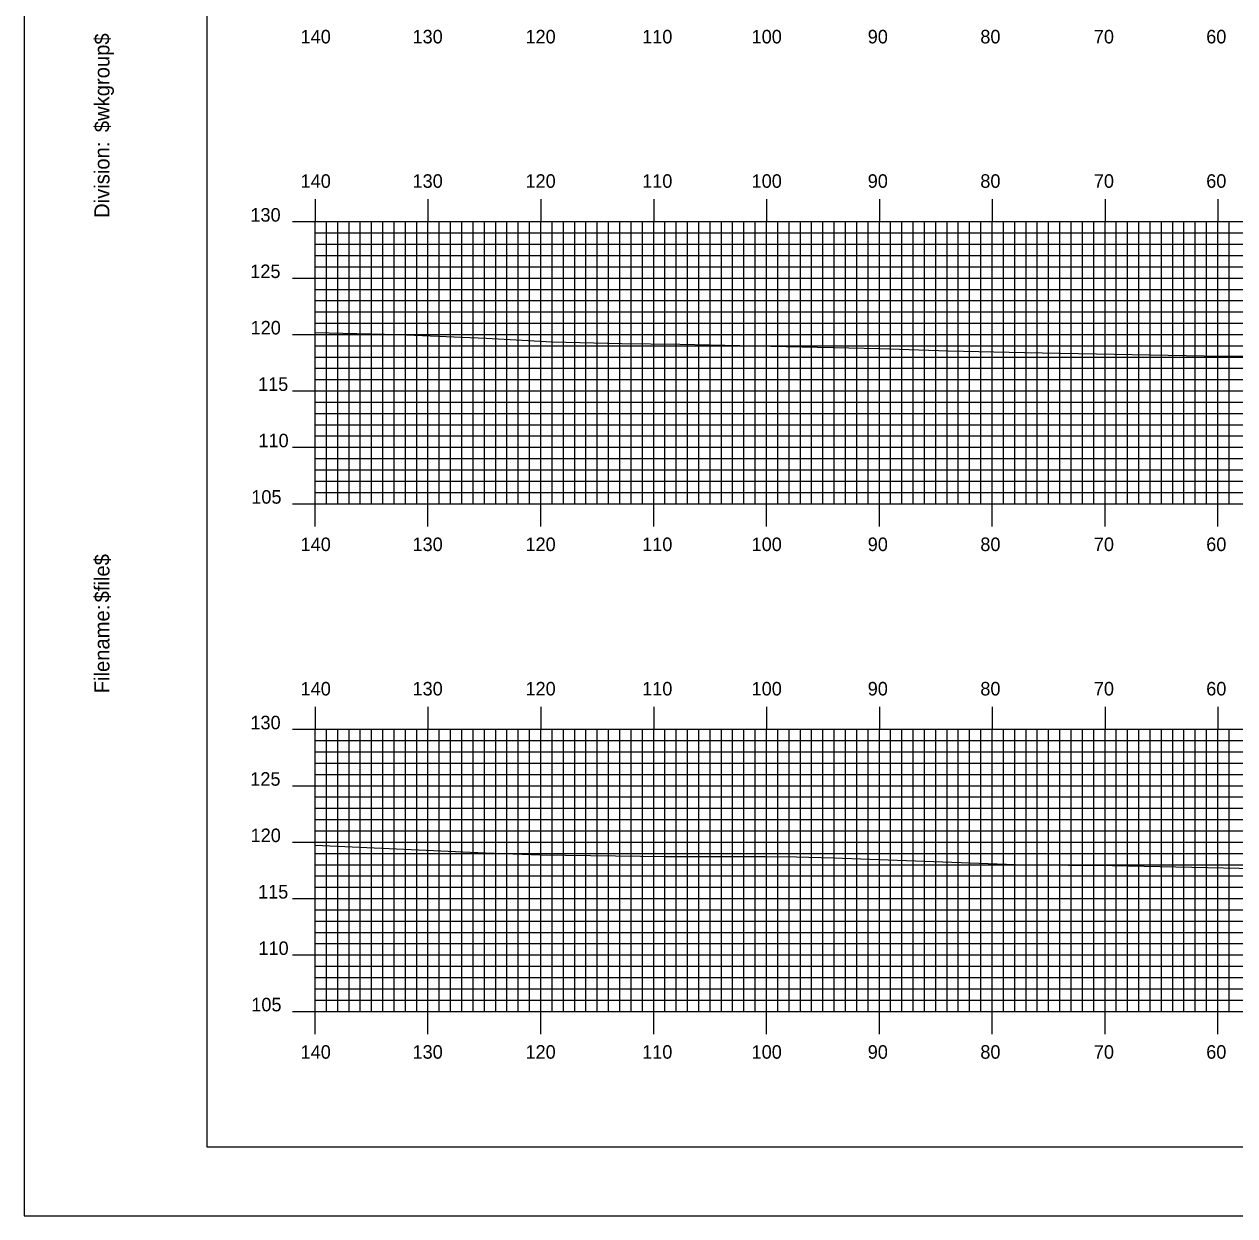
# Model space of a CAD drawing. Extents: x 1780680 to 1781023, y 442591 to 442811.
# Drawn here: x 1780679.6 to 1780786.9, y 442590.5 to 442696.2 of the extents above; entities that cross this region are included whole.
import ezdxf

# ---------------------------------------------------------------- set-up
doc = ezdxf.new("R2010")
doc.units = 0
for name, color, linetype in [('BORDER', 7, 'Continuous'), ('H_V ANNOTATION', 7, 'Continuous'), ('MAJOR', 7, 'Continuous'), ('MINOR', 7, 'Continuous'), ('PLOT BOUNDARY', 7, 'Continuous'), ('S_Roadway_Centerline', 7, 'Continuous')]:
    doc.layers.add(name, color=color, linetype=linetype)

msp = doc.modelspace()

# ---------------------------------------------------------------- linework, layer by layer
at = {"layer": 'BORDER'}
msp.add_lwpolyline([(1780695.78, 442596.67), (1781015.78, 442596.67), (1781015.78, 442806.67), (1780695.78, 442806.67)], close=True, dxfattribs=at)
at = {"layer": 'MAJOR'}
for p, q in [((1780705.38, 442680.67), (1780705.38, 442678.67)), ((1780715.38, 442680.67), (1780715.38, 442678.67)), ((1780725.38, 442680.67), (1780725.38, 442678.67)), ((1780735.38, 442680.67), (1780735.38, 442678.67)), ((1780745.38, 442680.67), (1780745.38, 442678.67)), ((1780755.38, 442680.67), (1780755.38, 442678.67)), ((1780765.38, 442680.67), (1780765.38, 442678.67)), ((1780775.38, 442680.67), (1780775.38, 442678.67)), ((1780785.38, 442680.67), (1780785.38, 442678.67)), ((1780703.38, 442678.67), (1780705.38, 442678.67)), ((1780705.38, 442678.67), (1780985.38, 442678.67)), ((1780705.38, 442653.67), (1780705.38, 442678.67)), ((1780705.38, 442653.67), (1780705.38, 442678.67)), ((1780705.38, 442678.67), (1780985.38, 442678.67)), ((1780715.38, 442653.67), (1780715.38, 442678.67)), ((1780725.38, 442653.67), (1780725.38, 442678.67)), ((1780735.38, 442653.67), (1780735.38, 442678.67)), ((1780745.38, 442653.67), (1780745.38, 442678.67)), ((1780755.38, 442653.67), (1780755.38, 442678.67)), ((1780765.38, 442653.67), (1780765.38, 442678.67)), ((1780775.38, 442653.67), (1780775.38, 442678.67)), ((1780785.38, 442653.67), (1780785.38, 442678.67)), ((1780703.38, 442673.67), (1780705.38, 442673.67)), ((1780705.38, 442673.67), (1780985.38, 442673.67)), ((1780703.38, 442668.67), (1780705.38, 442668.67)), ((1780705.38, 442668.67), (1780985.38, 442668.67)), ((1780703.38, 442663.67), (1780705.38, 442663.67)), ((1780705.38, 442663.67), (1780985.38, 442663.67)), ((1780703.38, 442658.67), (1780705.38, 442658.67)), ((1780705.38, 442658.67), (1780985.38, 442658.67)), ((1780703.38, 442653.67), (1780705.38, 442653.67)), ((1780705.38, 442653.67), (1780985.38, 442653.67)), ((1780705.38, 442653.67), (1780985.38, 442653.67)), ((1780705.38, 442651.66), (1780705.38, 442653.67)), ((1780715.38, 442651.66), (1780715.38, 442653.67)), ((1780725.38, 442651.66), (1780725.38, 442653.67)), ((1780735.38, 442651.66), (1780735.38, 442653.67)), ((1780745.38, 442651.66), (1780745.38, 442653.67)), ((1780755.38, 442651.66), (1780755.38, 442653.67)), ((1780765.38, 442651.66), (1780765.38, 442653.67)), ((1780775.38, 442651.66), (1780775.38, 442653.67)), ((1780785.38, 442651.66), (1780785.38, 442653.67)), ((1780705.38, 442635.67), (1780705.38, 442633.67)), ((1780715.38, 442635.67), (1780715.38, 442633.67)), ((1780725.38, 442635.67), (1780725.38, 442633.67)), ((1780735.38, 442635.67), (1780735.38, 442633.67)), ((1780745.38, 442635.67), (1780745.38, 442633.67)), ((1780755.38, 442635.67), (1780755.38, 442633.67)), ((1780765.38, 442635.67), (1780765.38, 442633.67)), ((1780775.38, 442635.67), (1780775.38, 442633.67)), ((1780785.38, 442635.67), (1780785.38, 442633.67)), ((1780703.38, 442633.67), (1780705.38, 442633.67)), ((1780705.38, 442633.67), (1780985.38, 442633.67)), ((1780705.38, 442608.67), (1780705.38, 442633.67)), ((1780705.38, 442608.67), (1780705.38, 442633.67)), ((1780705.38, 442633.67), (1780985.38, 442633.67)), ((1780715.38, 442608.67), (1780715.38, 442633.67)), ((1780725.38, 442608.67), (1780725.38, 442633.67)), ((1780735.38, 442608.67), (1780735.38, 442633.67)), ((1780745.38, 442608.67), (1780745.38, 442633.67)), ((1780755.38, 442608.67), (1780755.38, 442633.67)), ((1780765.38, 442608.67), (1780765.38, 442633.67)), ((1780775.38, 442608.67), (1780775.38, 442633.67)), ((1780785.38, 442608.67), (1780785.38, 442633.67)), ((1780703.38, 442628.67), (1780705.38, 442628.67)), ((1780705.38, 442628.67), (1780985.38, 442628.67)), ((1780703.38, 442623.67), (1780705.38, 442623.67)), ((1780705.38, 442623.67), (1780985.38, 442623.67)), ((1780703.38, 442618.67), (1780705.38, 442618.67)), ((1780705.38, 442618.67), (1780985.38, 442618.67)), ((1780703.38, 442613.67), (1780705.38, 442613.67)), ((1780705.38, 442613.67), (1780985.38, 442613.67)), ((1780703.38, 442608.67), (1780705.38, 442608.67)), ((1780705.38, 442608.67), (1780985.38, 442608.67)), ((1780705.38, 442608.67), (1780985.38, 442608.67)), ((1780705.38, 442606.66), (1780705.38, 442608.67)), ((1780715.38, 442606.66), (1780715.38, 442608.67)), ((1780725.38, 442606.66), (1780725.38, 442608.67)), ((1780735.38, 442606.66), (1780735.38, 442608.67)), ((1780745.38, 442606.66), (1780745.38, 442608.67)), ((1780755.38, 442606.66), (1780755.38, 442608.67)), ((1780765.38, 442606.66), (1780765.38, 442608.67)), ((1780775.38, 442606.66), (1780775.38, 442608.67)), ((1780785.38, 442606.66), (1780785.38, 442608.67))]:
    msp.add_line(p, q, dxfattribs=at)
at = {"layer": 'MINOR'}
for p, q in [((1780706.38, 442653.67), (1780706.38, 442678.67)), ((1780707.38, 442653.67), (1780707.38, 442678.67)), ((1780708.38, 442653.67), (1780708.38, 442678.67)), ((1780709.38, 442653.67), (1780709.38, 442678.67)), ((1780710.38, 442653.67), (1780710.38, 442678.67)), ((1780711.38, 442653.67), (1780711.38, 442678.67)), ((1780712.38, 442653.67), (1780712.38, 442678.67)), ((1780713.38, 442653.67), (1780713.38, 442678.67)), ((1780714.38, 442653.67), (1780714.38, 442678.67)), ((1780716.38, 442653.67), (1780716.38, 442678.67)), ((1780717.38, 442653.67), (1780717.38, 442678.67)), ((1780718.38, 442653.67), (1780718.38, 442678.67)), ((1780719.38, 442653.67), (1780719.38, 442678.67)), ((1780720.38, 442653.67), (1780720.38, 442678.67)), ((1780721.38, 442653.67), (1780721.38, 442678.67)), ((1780722.38, 442653.67), (1780722.38, 442678.67)), ((1780723.38, 442653.67), (1780723.38, 442678.67)), ((1780724.38, 442653.67), (1780724.38, 442678.67)), ((1780726.38, 442653.67), (1780726.38, 442678.67)), ((1780727.38, 442653.67), (1780727.38, 442678.67)), ((1780728.38, 442653.67), (1780728.38, 442678.67)), ((1780729.38, 442653.67), (1780729.38, 442678.67)), ((1780730.38, 442653.67), (1780730.38, 442678.67)), ((1780731.38, 442653.67), (1780731.38, 442678.67)), ((1780732.38, 442653.67), (1780732.38, 442678.67)), ((1780733.38, 442653.67), (1780733.38, 442678.67)), ((1780734.38, 442653.67), (1780734.38, 442678.67)), ((1780736.38, 442653.67), (1780736.38, 442678.67)), ((1780737.38, 442653.67), (1780737.38, 442678.67)), ((1780738.38, 442653.67), (1780738.38, 442678.67)), ((1780739.38, 442653.67), (1780739.38, 442678.67)), ((1780740.38, 442653.67), (1780740.38, 442678.67)), ((1780741.38, 442653.67), (1780741.38, 442678.67)), ((1780742.38, 442653.67), (1780742.38, 442678.67)), ((1780743.38, 442653.67), (1780743.38, 442678.67)), ((1780744.38, 442653.67), (1780744.38, 442678.67)), ((1780746.38, 442653.67), (1780746.38, 442678.67)), ((1780747.38, 442653.67), (1780747.38, 442678.67)), ((1780748.38, 442653.67), (1780748.38, 442678.67)), ((1780749.38, 442653.67), (1780749.38, 442678.67)), ((1780750.38, 442653.67), (1780750.38, 442678.67)), ((1780751.38, 442653.67), (1780751.38, 442678.67)), ((1780752.38, 442653.67), (1780752.38, 442678.67)), ((1780753.38, 442653.67), (1780753.38, 442678.67)), ((1780754.38, 442653.67), (1780754.38, 442678.67)), ((1780756.38, 442653.67), (1780756.38, 442678.67)), ((1780757.38, 442653.67), (1780757.38, 442678.67)), ((1780758.38, 442653.67), (1780758.38, 442678.67)), ((1780759.38, 442653.67), (1780759.38, 442678.67)), ((1780760.38, 442653.67), (1780760.38, 442678.67)), ((1780761.38, 442653.67), (1780761.38, 442678.67)), ((1780762.38, 442653.67), (1780762.38, 442678.67)), ((1780763.38, 442653.67), (1780763.38, 442678.67)), ((1780764.38, 442653.67), (1780764.38, 442678.67)), ((1780766.38, 442653.67), (1780766.38, 442678.67)), ((1780767.38, 442653.67), (1780767.38, 442678.67)), ((1780768.38, 442653.67), (1780768.38, 442678.67)), ((1780769.38, 442653.67), (1780769.38, 442678.67)), ((1780770.38, 442653.67), (1780770.38, 442678.67)), ((1780771.38, 442653.67), (1780771.38, 442678.67)), ((1780772.38, 442653.67), (1780772.38, 442678.67)), ((1780773.38, 442653.67), (1780773.38, 442678.67)), ((1780774.38, 442653.67), (1780774.38, 442678.67)), ((1780776.38, 442653.67), (1780776.38, 442678.67)), ((1780777.38, 442653.67), (1780777.38, 442678.67)), ((1780778.38, 442653.67), (1780778.38, 442678.67)), ((1780779.38, 442653.67), (1780779.38, 442678.67)), ((1780780.38, 442653.67), (1780780.38, 442678.67)), ((1780781.38, 442653.67), (1780781.38, 442678.67)), ((1780782.38, 442653.67), (1780782.38, 442678.67)), ((1780783.38, 442653.67), (1780783.38, 442678.67)), ((1780784.38, 442653.67), (1780784.38, 442678.67)), ((1780786.38, 442653.67), (1780786.38, 442678.67)), ((1780705.38, 442677.67), (1780985.38, 442677.67)), ((1780705.38, 442677.67), (1780707.39, 442677.67)), ((1780705.38, 442676.67), (1780985.38, 442676.67)), ((1780705.38, 442676.67), (1780707.39, 442676.67)), ((1780705.38, 442675.67), (1780985.38, 442675.67)), ((1780705.38, 442675.67), (1780707.39, 442675.67)), ((1780705.38, 442674.67), (1780985.38, 442674.67)), ((1780705.38, 442674.67), (1780707.39, 442674.67)), ((1780705.38, 442672.67), (1780985.38, 442672.67)), ((1780705.38, 442672.67), (1780707.39, 442672.67)), ((1780705.38, 442671.67), (1780985.38, 442671.67)), ((1780705.38, 442671.67), (1780707.39, 442671.67)), ((1780705.38, 442670.67), (1780985.38, 442670.67)), ((1780705.38, 442670.67), (1780707.39, 442670.67)), ((1780705.38, 442669.67), (1780985.38, 442669.67)), ((1780705.38, 442669.67), (1780707.39, 442669.67)), ((1780705.38, 442667.67), (1780985.38, 442667.67)), ((1780705.38, 442667.67), (1780707.39, 442667.67)), ((1780705.38, 442666.67), (1780985.38, 442666.67)), ((1780705.38, 442666.67), (1780707.39, 442666.67)), ((1780705.38, 442665.67), (1780985.38, 442665.67)), ((1780705.38, 442665.67), (1780707.39, 442665.67)), ((1780705.38, 442664.67), (1780985.38, 442664.67)), ((1780705.38, 442664.67), (1780707.39, 442664.67)), ((1780705.38, 442662.67), (1780985.38, 442662.67)), ((1780705.38, 442662.67), (1780707.39, 442662.67)), ((1780705.38, 442661.67), (1780985.38, 442661.67)), ((1780705.38, 442661.67), (1780707.39, 442661.67)), ((1780705.38, 442660.67), (1780985.38, 442660.67)), ((1780705.38, 442660.67), (1780707.39, 442660.67)), ((1780705.38, 442659.67), (1780985.38, 442659.67)), ((1780705.38, 442659.67), (1780707.39, 442659.67)), ((1780705.38, 442657.67), (1780985.38, 442657.67)), ((1780705.38, 442657.67), (1780707.39, 442657.67)), ((1780705.38, 442656.67), (1780985.38, 442656.67)), ((1780705.38, 442656.67), (1780707.39, 442656.67)), ((1780705.38, 442655.67), (1780985.38, 442655.67)), ((1780705.38, 442655.67), (1780707.39, 442655.67)), ((1780705.38, 442654.67), (1780985.38, 442654.67)), ((1780705.38, 442654.67), (1780707.39, 442654.67)), ((1780706.38, 442608.67), (1780706.38, 442633.67)), ((1780707.38, 442608.67), (1780707.38, 442633.67)), ((1780708.38, 442608.67), (1780708.38, 442633.67)), ((1780709.38, 442608.67), (1780709.38, 442633.67)), ((1780710.38, 442608.67), (1780710.38, 442633.67)), ((1780711.38, 442608.67), (1780711.38, 442633.67)), ((1780712.38, 442608.67), (1780712.38, 442633.67)), ((1780713.38, 442608.67), (1780713.38, 442633.67)), ((1780714.38, 442608.67), (1780714.38, 442633.67)), ((1780716.38, 442608.67), (1780716.38, 442633.67)), ((1780717.38, 442608.67), (1780717.38, 442633.67)), ((1780718.38, 442608.67), (1780718.38, 442633.67)), ((1780719.38, 442608.67), (1780719.38, 442633.67)), ((1780720.38, 442608.67), (1780720.38, 442633.67)), ((1780721.38, 442608.67), (1780721.38, 442633.67)), ((1780722.38, 442608.67), (1780722.38, 442633.67)), ((1780723.38, 442608.67), (1780723.38, 442633.67)), ((1780724.38, 442608.67), (1780724.38, 442633.67)), ((1780726.38, 442608.67), (1780726.38, 442633.67)), ((1780727.38, 442608.67), (1780727.38, 442633.67)), ((1780728.38, 442608.67), (1780728.38, 442633.67)), ((1780729.38, 442608.67), (1780729.38, 442633.67)), ((1780730.38, 442608.67), (1780730.38, 442633.67)), ((1780731.38, 442608.67), (1780731.38, 442633.67)), ((1780732.38, 442608.67), (1780732.38, 442633.67)), ((1780733.38, 442608.67), (1780733.38, 442633.67)), ((1780734.38, 442608.67), (1780734.38, 442633.67)), ((1780736.38, 442608.67), (1780736.38, 442633.67)), ((1780737.38, 442608.67), (1780737.38, 442633.67)), ((1780738.38, 442608.67), (1780738.38, 442633.67)), ((1780739.38, 442608.67), (1780739.38, 442633.67)), ((1780740.38, 442608.67), (1780740.38, 442633.67)), ((1780741.38, 442608.67), (1780741.38, 442633.67)), ((1780742.38, 442608.67), (1780742.38, 442633.67)), ((1780743.38, 442608.67), (1780743.38, 442633.67)), ((1780744.38, 442608.67), (1780744.38, 442633.67)), ((1780746.38, 442608.67), (1780746.38, 442633.67)), ((1780747.38, 442608.67), (1780747.38, 442633.67)), ((1780748.38, 442608.67), (1780748.38, 442633.67)), ((1780749.38, 442608.67), (1780749.38, 442633.67)), ((1780750.38, 442608.67), (1780750.38, 442633.67)), ((1780751.38, 442608.67), (1780751.38, 442633.67)), ((1780752.38, 442608.67), (1780752.38, 442633.67)), ((1780753.38, 442608.67), (1780753.38, 442633.67)), ((1780754.38, 442608.67), (1780754.38, 442633.67)), ((1780756.38, 442608.67), (1780756.38, 442633.67)), ((1780757.38, 442608.67), (1780757.38, 442633.67)), ((1780758.38, 442608.67), (1780758.38, 442633.67)), ((1780759.38, 442608.67), (1780759.38, 442633.67)), ((1780760.38, 442608.67), (1780760.38, 442633.67)), ((1780761.38, 442608.67), (1780761.38, 442633.67)), ((1780762.38, 442608.67), (1780762.38, 442633.67)), ((1780763.38, 442608.67), (1780763.38, 442633.67)), ((1780764.38, 442608.67), (1780764.38, 442633.67)), ((1780766.38, 442608.67), (1780766.38, 442633.67)), ((1780767.38, 442608.67), (1780767.38, 442633.67)), ((1780768.38, 442608.67), (1780768.38, 442633.67)), ((1780769.38, 442608.67), (1780769.38, 442633.67)), ((1780770.38, 442608.67), (1780770.38, 442633.67)), ((1780771.38, 442608.67), (1780771.38, 442633.67)), ((1780772.38, 442608.67), (1780772.38, 442633.67)), ((1780773.38, 442608.67), (1780773.38, 442633.67)), ((1780774.38, 442608.67), (1780774.38, 442633.67)), ((1780776.38, 442608.67), (1780776.38, 442633.67)), ((1780777.38, 442608.67), (1780777.38, 442633.67)), ((1780778.38, 442608.67), (1780778.38, 442633.67)), ((1780779.38, 442608.67), (1780779.38, 442633.67)), ((1780780.38, 442608.67), (1780780.38, 442633.67)), ((1780781.38, 442608.67), (1780781.38, 442633.67)), ((1780782.38, 442608.67), (1780782.38, 442633.67)), ((1780783.38, 442608.67), (1780783.38, 442633.67)), ((1780784.38, 442608.67), (1780784.38, 442633.67)), ((1780786.38, 442608.67), (1780786.38, 442633.67)), ((1780705.38, 442632.67), (1780985.38, 442632.67)), ((1780705.38, 442632.67), (1780707.39, 442632.67)), ((1780705.38, 442631.67), (1780985.38, 442631.67)), ((1780705.38, 442631.67), (1780707.39, 442631.67)), ((1780705.38, 442630.67), (1780985.38, 442630.67)), ((1780705.38, 442630.67), (1780707.39, 442630.67)), ((1780705.38, 442629.67), (1780985.38, 442629.67)), ((1780705.38, 442629.67), (1780707.39, 442629.67)), ((1780705.38, 442627.67), (1780985.38, 442627.67)), ((1780705.38, 442627.67), (1780707.39, 442627.67)), ((1780705.38, 442626.67), (1780985.38, 442626.67)), ((1780705.38, 442626.67), (1780707.39, 442626.67)), ((1780705.38, 442625.67), (1780985.38, 442625.67)), ((1780705.38, 442625.67), (1780707.39, 442625.67)), ((1780705.38, 442624.67), (1780985.38, 442624.67)), ((1780705.38, 442624.67), (1780707.39, 442624.67)), ((1780705.38, 442622.67), (1780985.38, 442622.67)), ((1780705.38, 442622.67), (1780707.39, 442622.67)), ((1780705.38, 442621.67), (1780985.38, 442621.67)), ((1780705.38, 442621.67), (1780707.39, 442621.67)), ((1780705.38, 442620.67), (1780985.38, 442620.67)), ((1780705.38, 442620.67), (1780707.39, 442620.67)), ((1780705.38, 442619.67), (1780985.38, 442619.67)), ((1780705.38, 442619.67), (1780707.39, 442619.67)), ((1780705.38, 442617.67), (1780985.38, 442617.67)), ((1780705.38, 442617.67), (1780707.39, 442617.67)), ((1780705.38, 442616.67), (1780985.38, 442616.67)), ((1780705.38, 442616.67), (1780707.39, 442616.67)), ((1780705.38, 442615.67), (1780985.38, 442615.67)), ((1780705.38, 442615.67), (1780707.39, 442615.67)), ((1780705.38, 442614.67), (1780985.38, 442614.67)), ((1780705.38, 442614.67), (1780707.39, 442614.67)), ((1780705.38, 442612.67), (1780985.38, 442612.67)), ((1780705.38, 442612.67), (1780707.39, 442612.67)), ((1780705.38, 442611.67), (1780985.38, 442611.67)), ((1780705.38, 442611.67), (1780707.39, 442611.67)), ((1780705.38, 442610.67), (1780985.38, 442610.67)), ((1780705.38, 442610.67), (1780707.39, 442610.67)), ((1780705.38, 442609.67), (1780985.38, 442609.67)), ((1780705.38, 442609.67), (1780707.39, 442609.67))]:
    msp.add_line(p, q, dxfattribs=at)
at = {"layer": 'PLOT BOUNDARY'}
msp.add_lwpolyline([(1780679.59, 442590.55), (1781019.59, 442590.55), (1781019.59, 442810.55), (1780679.59, 442810.55)], close=True, dxfattribs=at)
at = {"layer": 'S_Roadway_Centerline'}
for points in [[(1780705.38, 442668.83), (1780712.77, 442668.67), (1780720.55, 442668.34), (1780726.37, 442668.03), (1780732.52, 442667.88), (1780737.7, 442667.81), (1780743.03, 442667.7), (1780755.43, 442667.42), (1780761.49, 442667.21), (1780768.25, 442667.06), (1780784.17, 442666.78), (1780788.2, 442666.76)], [(1780705.38, 442623.4), (1780720.45, 442622.71), (1780722.91, 442622.63), (1780725.35, 442622.54), (1780736.43, 442622.39), (1780745.25, 442622.39), (1780748.03, 442622.38), (1780751.33, 442622.29), (1780760.22, 442621.96), (1780768.24, 442621.65), (1780776.03, 442621.59), (1780788.7, 442621.33)]]:
    msp.add_lwpolyline(points, dxfattribs=at)

# ---------------------------------------------------------------- texts
at = {"layer": 'BORDER'}
for s, p in [('$wkgroup$', (1780687.15, 442686.6)), ('Division:', (1780687.15, 442679)), ('$file$', (1780687.15, 442644.92)), ('Filename:', (1780687.15, 442636.86))]:
    msp.add_text(s, height=1.339, rotation=90, dxfattribs=at).set_placement(p)
at = {"layer": 'H_V ANNOTATION'}
for s, p in [('140', (1780704.09, 442694.47)), ('130', (1780714.01, 442694.47)), ('120', (1780724.02, 442694.47)), ('110', (1780734.36, 442694.47)), ('100', (1780744.06, 442694.47)), ('90', (1780754.35, 442694.47)), ('80', (1780764.33, 442694.47)), ('70', (1780774.39, 442694.47)), ('60', (1780784.35, 442694.47)), ('140', (1780704.09, 442681.67)), ('130', (1780714.01, 442681.67)), ('120', (1780724.02, 442681.67)), ('110', (1780734.36, 442681.67)), ('100', (1780744.06, 442681.67)), ('90', (1780754.35, 442681.67)), ('80', (1780764.33, 442681.67)), ('70', (1780774.39, 442681.67)), ('60', (1780784.35, 442681.67)), ('130', (1780699.64, 442678.67)), ('125', (1780699.63, 442673.67)), ('120', (1780699.66, 442668.67)), ('115', (1780700.32, 442663.67)), ('110', (1780700.35, 442658.67)), ('105', (1780699.72, 442653.67)), ('140', (1780704.09, 442649.47)), ('130', (1780714.01, 442649.47)), ('120', (1780724.02, 442649.47)), ('110', (1780734.36, 442649.47)), ('100', (1780744.06, 442649.47)), ('90', (1780754.35, 442649.47)), ('80', (1780764.33, 442649.47)), ('70', (1780774.39, 442649.47)), ('60', (1780784.35, 442649.47)), ('140', (1780704.09, 442636.67)), ('130', (1780714.01, 442636.67)), ('120', (1780724.02, 442636.67)), ('110', (1780734.36, 442636.67)), ('100', (1780744.06, 442636.67)), ('90', (1780754.35, 442636.67)), ('80', (1780764.33, 442636.67)), ('70', (1780774.39, 442636.67)), ('60', (1780784.35, 442636.67)), ('130', (1780699.64, 442633.67)), ('125', (1780699.63, 442628.67)), ('120', (1780699.66, 442623.67)), ('115', (1780700.32, 442618.67)), ('110', (1780700.35, 442613.67)), ('105', (1780699.72, 442608.67)), ('140', (1780704.09, 442604.47)), ('130', (1780714.01, 442604.47)), ('120', (1780724.02, 442604.47)), ('110', (1780734.36, 442604.47)), ('100', (1780744.06, 442604.47)), ('90', (1780754.35, 442604.47)), ('80', (1780764.33, 442604.47)), ('70', (1780774.39, 442604.47)), ('60', (1780784.35, 442604.47))]:
    msp.add_text(s, height=1.2, dxfattribs=at).set_placement(p)
at = {"layer": 'MAJOR'}
for p in [(1780705.37, 442653.67), (1780705.37, 442608.67)]:
    msp.add_text('-', height=0.012, dxfattribs=at).set_placement(p)

doc.saveas('drawing.dxf')
